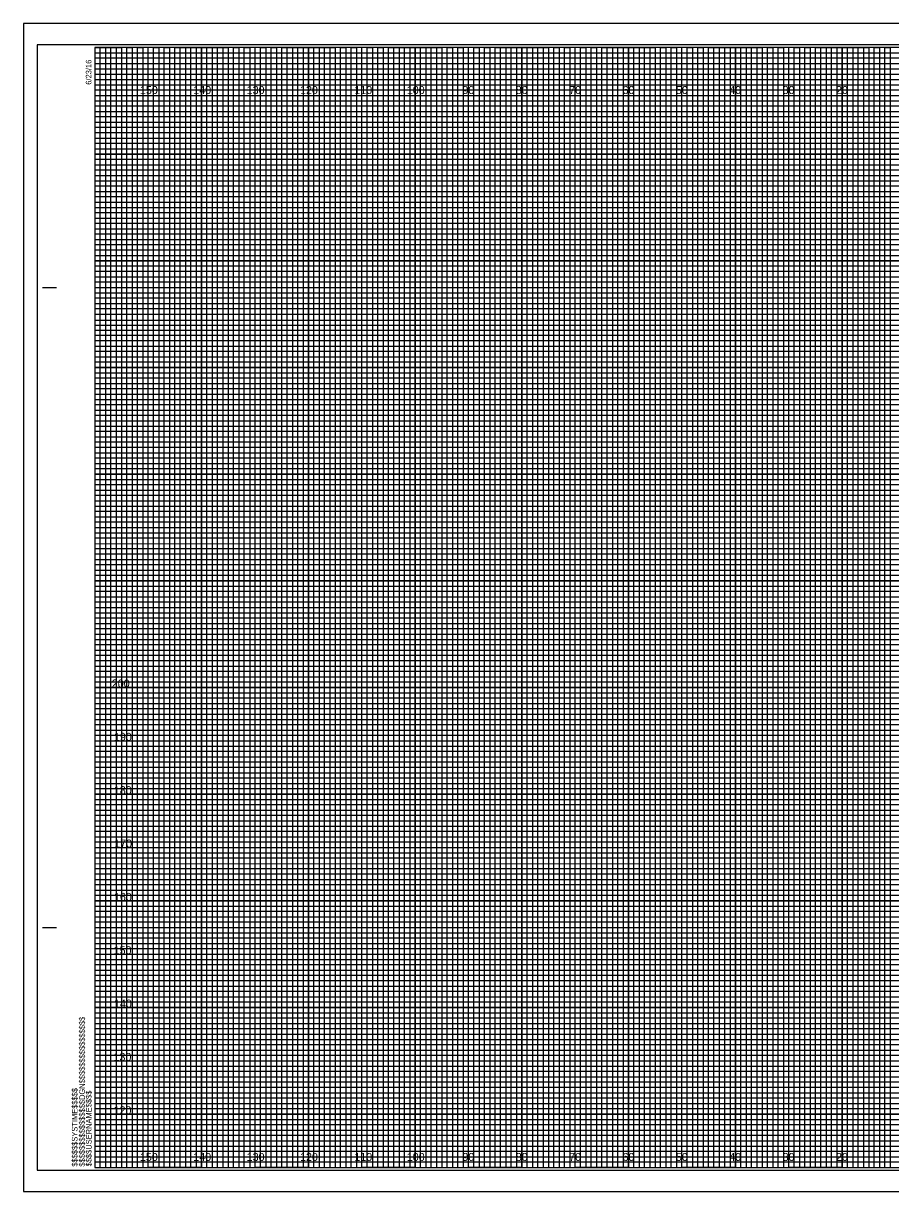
# Model space of a CAD drawing. Extents: x -13 to 323, y -5 to 4174.
# Drawn here: x -13.4 to 149.1, y 1535.5 to 1754.5 of the extents above; entities that cross this region are included whole.
import ezdxf

# ---------------------------------------------------------------- set-up
doc = ezdxf.new("R2010")
doc.units = 0
for name, color, linetype in [('Exist Cross Section Cell', 7, 'Continuous'), ('Exist XS Center Line Elevation Label', 7, 'Continuous'), ('Exist XS Ground Line', 7, 'Continuous'), ('Prop CMT Guardrail Graphics', 7, 'Continuous'), ('Prop CMT Pvmt Course 1', 7, 'Continuous'), ('Prop CMT Pvmt Course 2', 7, 'Continuous'), ('Prop CMT Pvmt Course 3', 7, 'Continuous'), ('Prop CMT Shld Paved Course 1', 7, 'Continuous'), ('Prop CMT Shld Paved Course 2', 7, 'Continuous'), ('Prop CMT Subgrade Earthwork', 7, 'Continuous'), ('Scratch_Level_0', 7, 'Continuous')]:
    doc.layers.add(name, color=color, linetype=linetype)

msp = doc.modelspace()

# ---------------------------------------------------------------- linework, layer by layer
at = {"layer": 'Exist XS Center Line Elevation Label'}
for points in [[(0, 1750), (5, 1750), (5, 1540), (15, 1540), (15, 1750), (25, 1750), (25, 1540), (35, 1540), (35, 1750), (45, 1750), (45, 1540), (55, 1540), (55, 1750), (65, 1750), (65, 1540), (75, 1540), (75, 1750), (85, 1750), (85, 1540), (95, 1540), (95, 1750), (105, 1750), (105, 1540), (115, 1540), (115, 1750), (125, 1750), (125, 1540), (135, 1540), (135, 1750), (145, 1750), (145, 1540), (155, 1540)], [(0, 1745), (275, 1745)], [(0, 1725), (320, 1725), (320, 1735), (0, 1735)], [(0, 1705), (320, 1705), (320, 1715), (0, 1715)], [(0, 1685), (320, 1685), (320, 1695), (0, 1695)], [(0, 1665), (320, 1665), (320, 1675), (0, 1675)], [(0, 1645), (320, 1645), (320, 1655), (0, 1655)], [(0, 1625), (320, 1625), (320, 1635), (0, 1635)], [(0, 1605), (320, 1605), (320, 1615), (0, 1615)], [(0, 1585), (320, 1585), (320, 1595), (0, 1595)], [(0, 1565), (320, 1565), (320, 1575), (0, 1575)], [(0, 1545), (320, 1545), (320, 1555), (0, 1555)]]:
    msp.add_lwpolyline(points, dxfattribs=at)
at = {"layer": 'Exist XS Ground Line'}
for p, q in [((10, 1750), (0, 1750)), ((10, 1540), (10, 1750)), ((30, 1750), (20, 1750)), ((20, 1750), (20, 1540)), ((30, 1540), (30, 1750)), ((50, 1750), (40, 1750)), ((40, 1750), (40, 1540)), ((50, 1540), (50, 1750)), ((70, 1750), (60, 1750)), ((60, 1750), (60, 1540)), ((70, 1540), (70, 1750)), ((90, 1750), (80, 1750)), ((80, 1750), (80, 1540)), ((90, 1540), (90, 1750)), ((110, 1750), (100, 1750)), ((100, 1750), (100, 1540)), ((110, 1540), (110, 1750)), ((130, 1750), (120, 1750)), ((120, 1750), (120, 1540)), ((130, 1540), (130, 1750)), ((150, 1750), (140, 1750)), ((140, 1750), (140, 1540)), ((20, 1540), (10, 1540)), ((40, 1540), (30, 1540)), ((60, 1540), (50, 1540)), ((80, 1540), (70, 1540)), ((100, 1540), (90, 1540)), ((120, 1540), (110, 1540)), ((140, 1540), (130, 1540))]:
    msp.add_line(p, q, dxfattribs=at)
for points in [[(0, 1740), (320, 1740), (320, 1730), (0, 1730)], [(0, 1720), (320, 1720), (320, 1710), (0, 1710)], [(0, 1700), (320, 1700), (320, 1690), (0, 1690)], [(0, 1680), (320, 1680), (320, 1670), (0, 1670)], [(0, 1660), (320, 1660), (320, 1650), (0, 1650)], [(0, 1640), (320, 1640), (320, 1630), (0, 1630)], [(0, 1620), (320, 1620), (320, 1610), (0, 1610)], [(0, 1600), (320, 1600), (320, 1590), (0, 1590)], [(0, 1580), (320, 1580), (320, 1570), (0, 1570)], [(0, 1560), (320, 1560), (320, 1550), (0, 1550)]]:
    msp.add_lwpolyline(points, dxfattribs=at)
at = {"layer": 'Prop CMT Pvmt Course 1'}
for p, q in [((323.3, 1754.5), (-13.4, 1754.5)), ((-13.4, 1754.5), (-13.4, 1535.5)), ((-13.4, 1535.5), (323.3, 1535.5))]:
    msp.add_line(p, q, dxfattribs=at)
at = {"layer": 'Prop CMT Pvmt Course 2'}
msp.add_lwpolyline([(-13.4, 1535.5), (323.3, 1535.5), (323.3, 1754.5), (-13.4, 1754.5)], close=True, dxfattribs=at)
at = {"layer": 'Prop CMT Pvmt Course 3'}
msp.add_lwpolyline([(-10.8, 1539.5), (322.4, 1539.5), (322.4, 1750.5), (-10.8, 1750.5)], close=True, dxfattribs=at)
at = {"layer": 'Prop CMT Shld Paved Course 1'}
for p, q in [((-9.8, 1705), (-7.3, 1705)), ((-9.7, 1705), (-7.2, 1705)), ((-9.8, 1585), (-7.3, 1585)), ((-9.7, 1585), (-7.2, 1585)), ((0, 1540), (0, 1540)), ((0, 1540), (0, 1540)), ((0, 1540), (0, 1540)), ((0, 1540), (0, 1540)), ((0, 1540), (0, 1540)), ((0, 1540), (0, 1540)), ((0, 1540), (0, 1540))]:
    msp.add_line(p, q, dxfattribs=at)
msp.add_lwpolyline([(320, 1750), (0, 1750), (0, 1540), (320, 1540)], close=True, dxfattribs=at)
at = {"layer": 'Prop CMT Shld Paved Course 2'}
for points in [[(0, 1540), (1, 1540), (1, 1750), (2, 1750), (2, 1540)], [(2, 1540), (3, 1540), (3, 1750), (4, 1750), (4, 1540)], [(5, 1540), (6, 1540), (6, 1750), (7, 1750), (7, 1540)], [(7, 1540), (8, 1540), (8, 1750), (9, 1750), (9, 1540)], [(10, 1540), (11, 1540), (11, 1750), (12, 1750), (12, 1540)], [(12, 1540), (13, 1540), (13, 1750), (14, 1750), (14, 1540)], [(15, 1540), (16, 1540), (16, 1750), (17, 1750), (17, 1540)], [(17, 1540), (18, 1540), (18, 1750), (19, 1750), (19, 1540)], [(20, 1540), (21, 1540), (21, 1750), (22, 1750), (22, 1540)], [(22, 1540), (23, 1540), (23, 1750), (24, 1750), (24, 1540)], [(25, 1540), (26, 1540), (26, 1750), (27, 1750), (27, 1540)], [(27, 1540), (28, 1540), (28, 1750), (29, 1750), (29, 1540)], [(30, 1540), (31, 1540), (31, 1750), (32, 1750), (32, 1540)], [(32, 1540), (33, 1540), (33, 1750), (34, 1750), (34, 1540)], [(35, 1540), (36, 1540), (36, 1750), (37, 1750), (37, 1540)], [(37, 1540), (38, 1540), (38, 1750), (39, 1750), (39, 1540)], [(40, 1540), (41, 1540), (41, 1750), (42, 1750), (42, 1540)], [(42, 1540), (43, 1540), (43, 1750), (44, 1750), (44, 1540)], [(45, 1540), (46, 1540), (46, 1750), (47, 1750), (47, 1540)], [(47, 1540), (48, 1540), (48, 1750), (49, 1750), (49, 1540)], [(50, 1540), (51, 1540), (51, 1750), (52, 1750), (52, 1540)], [(52, 1540), (53, 1540), (53, 1750), (54, 1750), (54, 1540)], [(55, 1540), (56, 1540), (56, 1750), (57, 1750), (57, 1540)], [(57, 1540), (58, 1540), (58, 1750), (59, 1750), (59, 1540)], [(60, 1540), (61, 1540), (61, 1750), (62, 1750), (62, 1540)], [(62, 1540), (63, 1540), (63, 1750), (64, 1750), (64, 1540)], [(65, 1540), (66, 1540), (66, 1750), (67, 1750), (67, 1540)], [(67, 1540), (68, 1540), (68, 1750), (69, 1750), (69, 1540)], [(70, 1540), (71, 1540), (71, 1750), (72, 1750), (72, 1540)], [(72, 1540), (73, 1540), (73, 1750), (74, 1750), (74, 1540)], [(75, 1540), (76, 1540), (76, 1750), (77, 1750), (77, 1540)], [(77, 1540), (78, 1540), (78, 1750), (79, 1750), (79, 1540)], [(80, 1540), (81, 1540), (81, 1750), (82, 1750), (82, 1540)], [(82, 1540), (83, 1540), (83, 1750), (84, 1750), (84, 1540)], [(85, 1540), (86, 1540), (86, 1750), (87, 1750), (87, 1540)], [(87, 1540), (88, 1540), (88, 1750), (89, 1750), (89, 1540)], [(90, 1540), (91, 1540), (91, 1750), (92, 1750), (92, 1540)], [(92, 1540), (93, 1540), (93, 1750), (94, 1750), (94, 1540)], [(95, 1540), (96, 1540), (96, 1750), (97, 1750), (97, 1540)], [(97, 1540), (98, 1540), (98, 1750), (99, 1750), (99, 1540)], [(100, 1540), (101, 1540), (101, 1750), (102, 1750), (102, 1540)], [(102, 1540), (103, 1540), (103, 1750), (104, 1750), (104, 1540)], [(105, 1540), (106, 1540), (106, 1750), (107, 1750), (107, 1540)], [(107, 1540), (108, 1540), (108, 1750), (109, 1750), (109, 1540)], [(110, 1540), (111, 1540), (111, 1750), (112, 1750), (112, 1540)], [(112, 1540), (113, 1540), (113, 1750), (114, 1750), (114, 1540)], [(115, 1540), (116, 1540), (116, 1750), (117, 1750), (117, 1540)], [(117, 1540), (118, 1540), (118, 1750), (119, 1750), (119, 1540)], [(120, 1540), (121, 1540), (121, 1750), (122, 1750), (122, 1540)], [(122, 1540), (123, 1540), (123, 1750), (124, 1750), (124, 1540)], [(125, 1540), (126, 1540), (126, 1750), (127, 1750), (127, 1540)], [(127, 1540), (128, 1540), (128, 1750), (129, 1750), (129, 1540)], [(130, 1540), (131, 1540), (131, 1750), (132, 1750), (132, 1540)], [(132, 1540), (133, 1540), (133, 1750), (134, 1750), (134, 1540)], [(135, 1540), (136, 1540), (136, 1750), (137, 1750), (137, 1540)], [(137, 1540), (138, 1540), (138, 1750), (139, 1750), (139, 1540)], [(140, 1540), (141, 1540), (141, 1750), (142, 1750), (142, 1540)], [(142, 1540), (143, 1540), (143, 1750), (144, 1750), (144, 1540)], [(145, 1540), (146, 1540), (146, 1750), (147, 1750), (147, 1540)], [(147, 1540), (148, 1540), (148, 1750), (149, 1750), (149, 1540)]]:
    msp.add_lwpolyline(points, dxfattribs=at)
at = {"layer": 'Prop CMT Subgrade Earthwork'}
for p, q in [((10, 1540), (10, 1750)), ((20, 1540), (20, 1750)), ((30, 1540), (30, 1750)), ((40, 1540), (40, 1750)), ((50, 1540), (50, 1750)), ((60, 1540), (60, 1750)), ((70, 1540), (70, 1750)), ((80, 1540), (80, 1750)), ((90, 1540), (90, 1750)), ((100, 1540), (100, 1750)), ((110, 1540), (110, 1750)), ((120, 1540), (120, 1750)), ((130, 1540), (130, 1750)), ((140, 1540), (140, 1750)), ((0, 1740), (320, 1740)), ((0, 1730), (320, 1730)), ((0, 1720), (320, 1720)), ((0, 1710), (320, 1710)), ((0, 1700), (320, 1700)), ((0, 1690), (320, 1690)), ((0, 1680), (320, 1680)), ((0, 1670), (320, 1670)), ((0, 1660), (320, 1660)), ((0, 1650), (320, 1650)), ((0, 1640), (320, 1640)), ((0, 1630), (320, 1630)), ((0, 1620), (320, 1620)), ((0, 1610), (320, 1610)), ((0, 1600), (320, 1600)), ((0, 1590), (320, 1590)), ((0, 1580), (320, 1580)), ((0, 1570), (320, 1570)), ((0, 1560), (320, 1560)), ((0, 1550), (320, 1550))]:
    msp.add_line(p, q, dxfattribs=at)
at = {"layer": 'Scratch_Level_0'}
for p, q in [((0, 1749), (260, 1749)), ((260, 1747.98), (0, 1747.98)), ((0, 1747.98), (0, 1747)), ((0, 1747), (260, 1747)), ((260, 1745.89), (0, 1745.89)), ((0, 1745.89), (0, 1744)), ((0, 1744), (320, 1744))]:
    msp.add_line(p, q, dxfattribs=at)
for points in [[(0, 1743), (270, 1743), (320, 1743), (320, 1742), (0, 1742)], [(0, 1741), (320, 1741), (320, 1739), (0, 1739)], [(0, 1738), (320, 1738), (320, 1737), (0, 1736.98)], [(0, 1736), (320, 1736), (320, 1734), (0, 1734)], [(0, 1733), (320, 1733), (320, 1732), (0, 1732)], [(0, 1731), (320, 1731), (320, 1729), (0, 1729)], [(0, 1728), (320, 1728), (320, 1727), (0, 1727)], [(0, 1726), (320, 1726), (320, 1724), (0, 1724)], [(0, 1723), (320, 1723), (320, 1722), (0, 1722)], [(0, 1721), (320, 1721), (320, 1719), (0, 1719)], [(0, 1718), (320, 1718), (320, 1717), (0, 1717)], [(0, 1716), (320, 1716), (320, 1713.95), (320, 1713), (320, 1712), (0, 1712)], [(0, 1714), (320, 1714), (320, 1713), (0, 1713)], [(0, 1711), (320, 1711), (320, 1709), (0, 1709.03)], [(0, 1709.03), (320, 1709), (320, 1708), (0, 1708)], [(0, 1707), (320, 1707), (320, 1706), (0, 1706)], [(0, 1704), (320, 1704), (320, 1703), (0, 1703)], [(0, 1702), (320, 1702), (320, 1701), (0, 1701)], [(-0.07, 1698.89), (320, 1698.89), (320, 1697.88), (-0.07, 1697.88)], [(0, 1697), (320, 1697), (320, 1696), (0, 1696)], [(0, 1694), (320, 1694), (320, 1693), (0, 1693)], [(0, 1692), (320, 1692), (320, 1691), (0, 1691)], [(0, 1689), (320, 1689), (320, 1688), (0, 1688)], [(0, 1687), (320, 1687), (320, 1686), (0, 1686)], [(0, 1684), (320, 1684), (320, 1683), (0, 1683)], [(0, 1682), (320, 1682), (320, 1681), (0, 1681)], [(0, 1679), (320, 1679), (319.99, 1677.98), (0, 1678)], [(0, 1677), (320, 1677), (320, 1676), (0, 1676)], [(0, 1674), (320, 1674), (320, 1673), (0, 1673)], [(0, 1672), (320, 1672), (320, 1671), (0, 1671)], [(0, 1669), (320, 1669), (320, 1668), (0, 1668)], [(0, 1667), (320, 1667), (320, 1666), (0, 1666)], [(0, 1664), (320, 1664), (320, 1663), (0, 1663)], [(0, 1662), (320, 1662), (320, 1661), (0, 1661)], [(0, 1659), (320, 1659), (320, 1658), (0, 1658)], [(0, 1656.99), (320.07, 1656.91), (320, 1656), (0, 1656)], [(0, 1654), (320, 1654), (320, 1653), (0, 1653)], [(0, 1652), (320, 1652), (320, 1651), (0, 1651)], [(0, 1649), (320, 1649), (320, 1648), (0, 1648)], [(0, 1647), (320, 1647), (320, 1646), (0, 1646)], [(0, 1644), (320, 1644), (320, 1643), (0, 1643)], [(0, 1642), (320, 1642), (320, 1641), (0, 1641)], [(0, 1639), (320, 1639), (320, 1638), (0, 1638)], [(0, 1637), (320, 1637), (320, 1636), (0, 1636)], [(0, 1634), (320, 1634), (320, 1633), (0, 1633)], [(0, 1632), (320, 1632), (320, 1631), (0, 1631)], [(0, 1629), (320, 1629), (320, 1628), (0, 1628)], [(0, 1627), (320, 1627), (320, 1626), (0, 1626)], [(0, 1624), (320, 1624), (320, 1623), (0, 1623)], [(0, 1622), (320, 1622), (320, 1621), (0, 1621)], [(0, 1619), (320, 1619), (319.99, 1617.98), (0, 1618)], [(0, 1617), (320, 1617), (320, 1616), (0, 1616)], [(0, 1614), (320, 1614), (320, 1613), (0, 1613)], [(0, 1612), (320, 1612), (320, 1611), (0, 1611)], [(0, 1609), (320, 1609), (320, 1608), (0, 1608)], [(0, 1607), (320, 1607), (320, 1606), (0, 1606)], [(0, 1604), (320, 1604), (320, 1603), (0, 1603)], [(0, 1602), (320, 1602), (320, 1601), (0, 1601)], [(0, 1599), (320, 1599), (320, 1598), (0, 1598)], [(0, 1596.99), (320.07, 1596.91), (320, 1596), (0, 1596)], [(0, 1594), (320, 1594), (320, 1593), (0, 1593)], [(0, 1592), (320, 1592), (320, 1591), (0, 1591)], [(0, 1589), (320, 1589), (320, 1588), (0, 1588)], [(0, 1587), (320, 1587), (320, 1586), (0, 1586)], [(0, 1584), (320, 1584), (320, 1583), (0, 1583)], [(0, 1582), (320, 1582), (320, 1581), (0, 1581)], [(0, 1579), (320, 1579), (320, 1578), (0, 1578)], [(0, 1577), (320, 1577), (320, 1576), (0, 1576)], [(0, 1574), (320, 1574), (320, 1573), (0, 1573)], [(0, 1572), (320, 1572), (320, 1571), (0, 1571)], [(0, 1569), (320, 1569), (320, 1568), (0, 1568)], [(0, 1567), (320, 1567), (320, 1566), (0, 1566)], [(0, 1564), (320, 1564), (320, 1563), (0, 1563)], [(0, 1562), (320, 1562), (320, 1561), (0, 1561)], [(0, 1559), (320, 1559), (320, 1558), (0, 1558)], [(0, 1557), (320, 1557), (320, 1556), (0, 1556)], [(0, 1554), (320, 1554), (320, 1553), (0, 1553)], [(0, 1552), (320, 1552), (320, 1551), (0, 1551)], [(0, 1549), (320, 1549), (320, 1548), (0, 1548)], [(0, 1547), (320, 1547), (320, 1546), (0, 1546)], [(0, 1544), (320, 1544), (320, 1543), (0, 1543)], [(0, 1542), (320, 1542), (320, 1541), (0, 1541)]]:
    msp.add_lwpolyline(points, dxfattribs=at)

# ---------------------------------------------------------------- texts
at = {"layer": 'Exist Cross Section Cell'}
for s, p in [('150', (8.44, 1741.25)), ('140', (18.44, 1741.25)), ('130', (28.44, 1741.25)), ('120', (38.44, 1741.25)), ('110', (48.62, 1741.25)), ('100', (58.44, 1741.25)), ('90', (68.86, 1741.25)), ('80', (78.86, 1741.25)), ('70', (88.86, 1741.25)), ('60', (98.86, 1741.25)), ('50', (108.86, 1741.25)), ('40', (118.86, 1741.25)), ('30', (128.86, 1741.25)), ('20', (138.86, 1741.25)), ('150', (8.44, 1541.25)), ('140', (18.44, 1541.25)), ('130', (28.44, 1541.25)), ('120', (38.44, 1541.25)), ('110', (48.62, 1541.25)), ('100', (58.44, 1541.25)), ('90', (68.86, 1541.25)), ('80', (78.86, 1541.25)), ('70', (88.86, 1541.25)), ('60', (98.86, 1541.25)), ('50', (108.86, 1541.25)), ('40', (118.86, 1541.25)), ('30', (128.86, 1541.25)), ('20', (138.86, 1541.25))]:
    msp.add_text(s, height=1.5, dxfattribs=at).set_placement(p)
at = {"layer": 'Prop CMT Guardrail Graphics'}
for s, p in [('200', (3.17, 1630)), ('190', (3.57, 1620)), ('180', (3.55, 1610)), ('170', (3.61, 1600)), ('160', (3.57, 1590)), ('150', (3.52, 1580)), ('140', (3.57, 1570)), ('130', (3.49, 1560)), ('120', (3.5, 1550))]:
    msp.add_text(s, height=1.5, dxfattribs=at).set_placement(p)
at = {"layer": 'Prop CMT Shld Paved Course 1'}
for s, p in [('6/23/16', (-0.65, 1743)), ('$$$$$$$$$$$$$$$$DGN$$$$$$$$$$$$$$$$', (-1.88, 1540.18)), ('$$$$$$SYSTIME$$$$$', (-3.26, 1540.18)), ('$$$$USERNAME$$$$', (-0.62, 1540.23))]:
    msp.add_text(s, height=1.05, rotation=90, dxfattribs=at).set_placement(p)

doc.saveas('drawing.dxf')
